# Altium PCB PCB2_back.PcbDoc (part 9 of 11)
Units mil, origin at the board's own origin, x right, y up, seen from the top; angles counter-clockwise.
Board outline 6299 x 3937 mil, 4 copper layers (TopLayer, GROUND, VCC, BottomLayer); 290 components, 470 nets, 2252 pads, 825 vias.
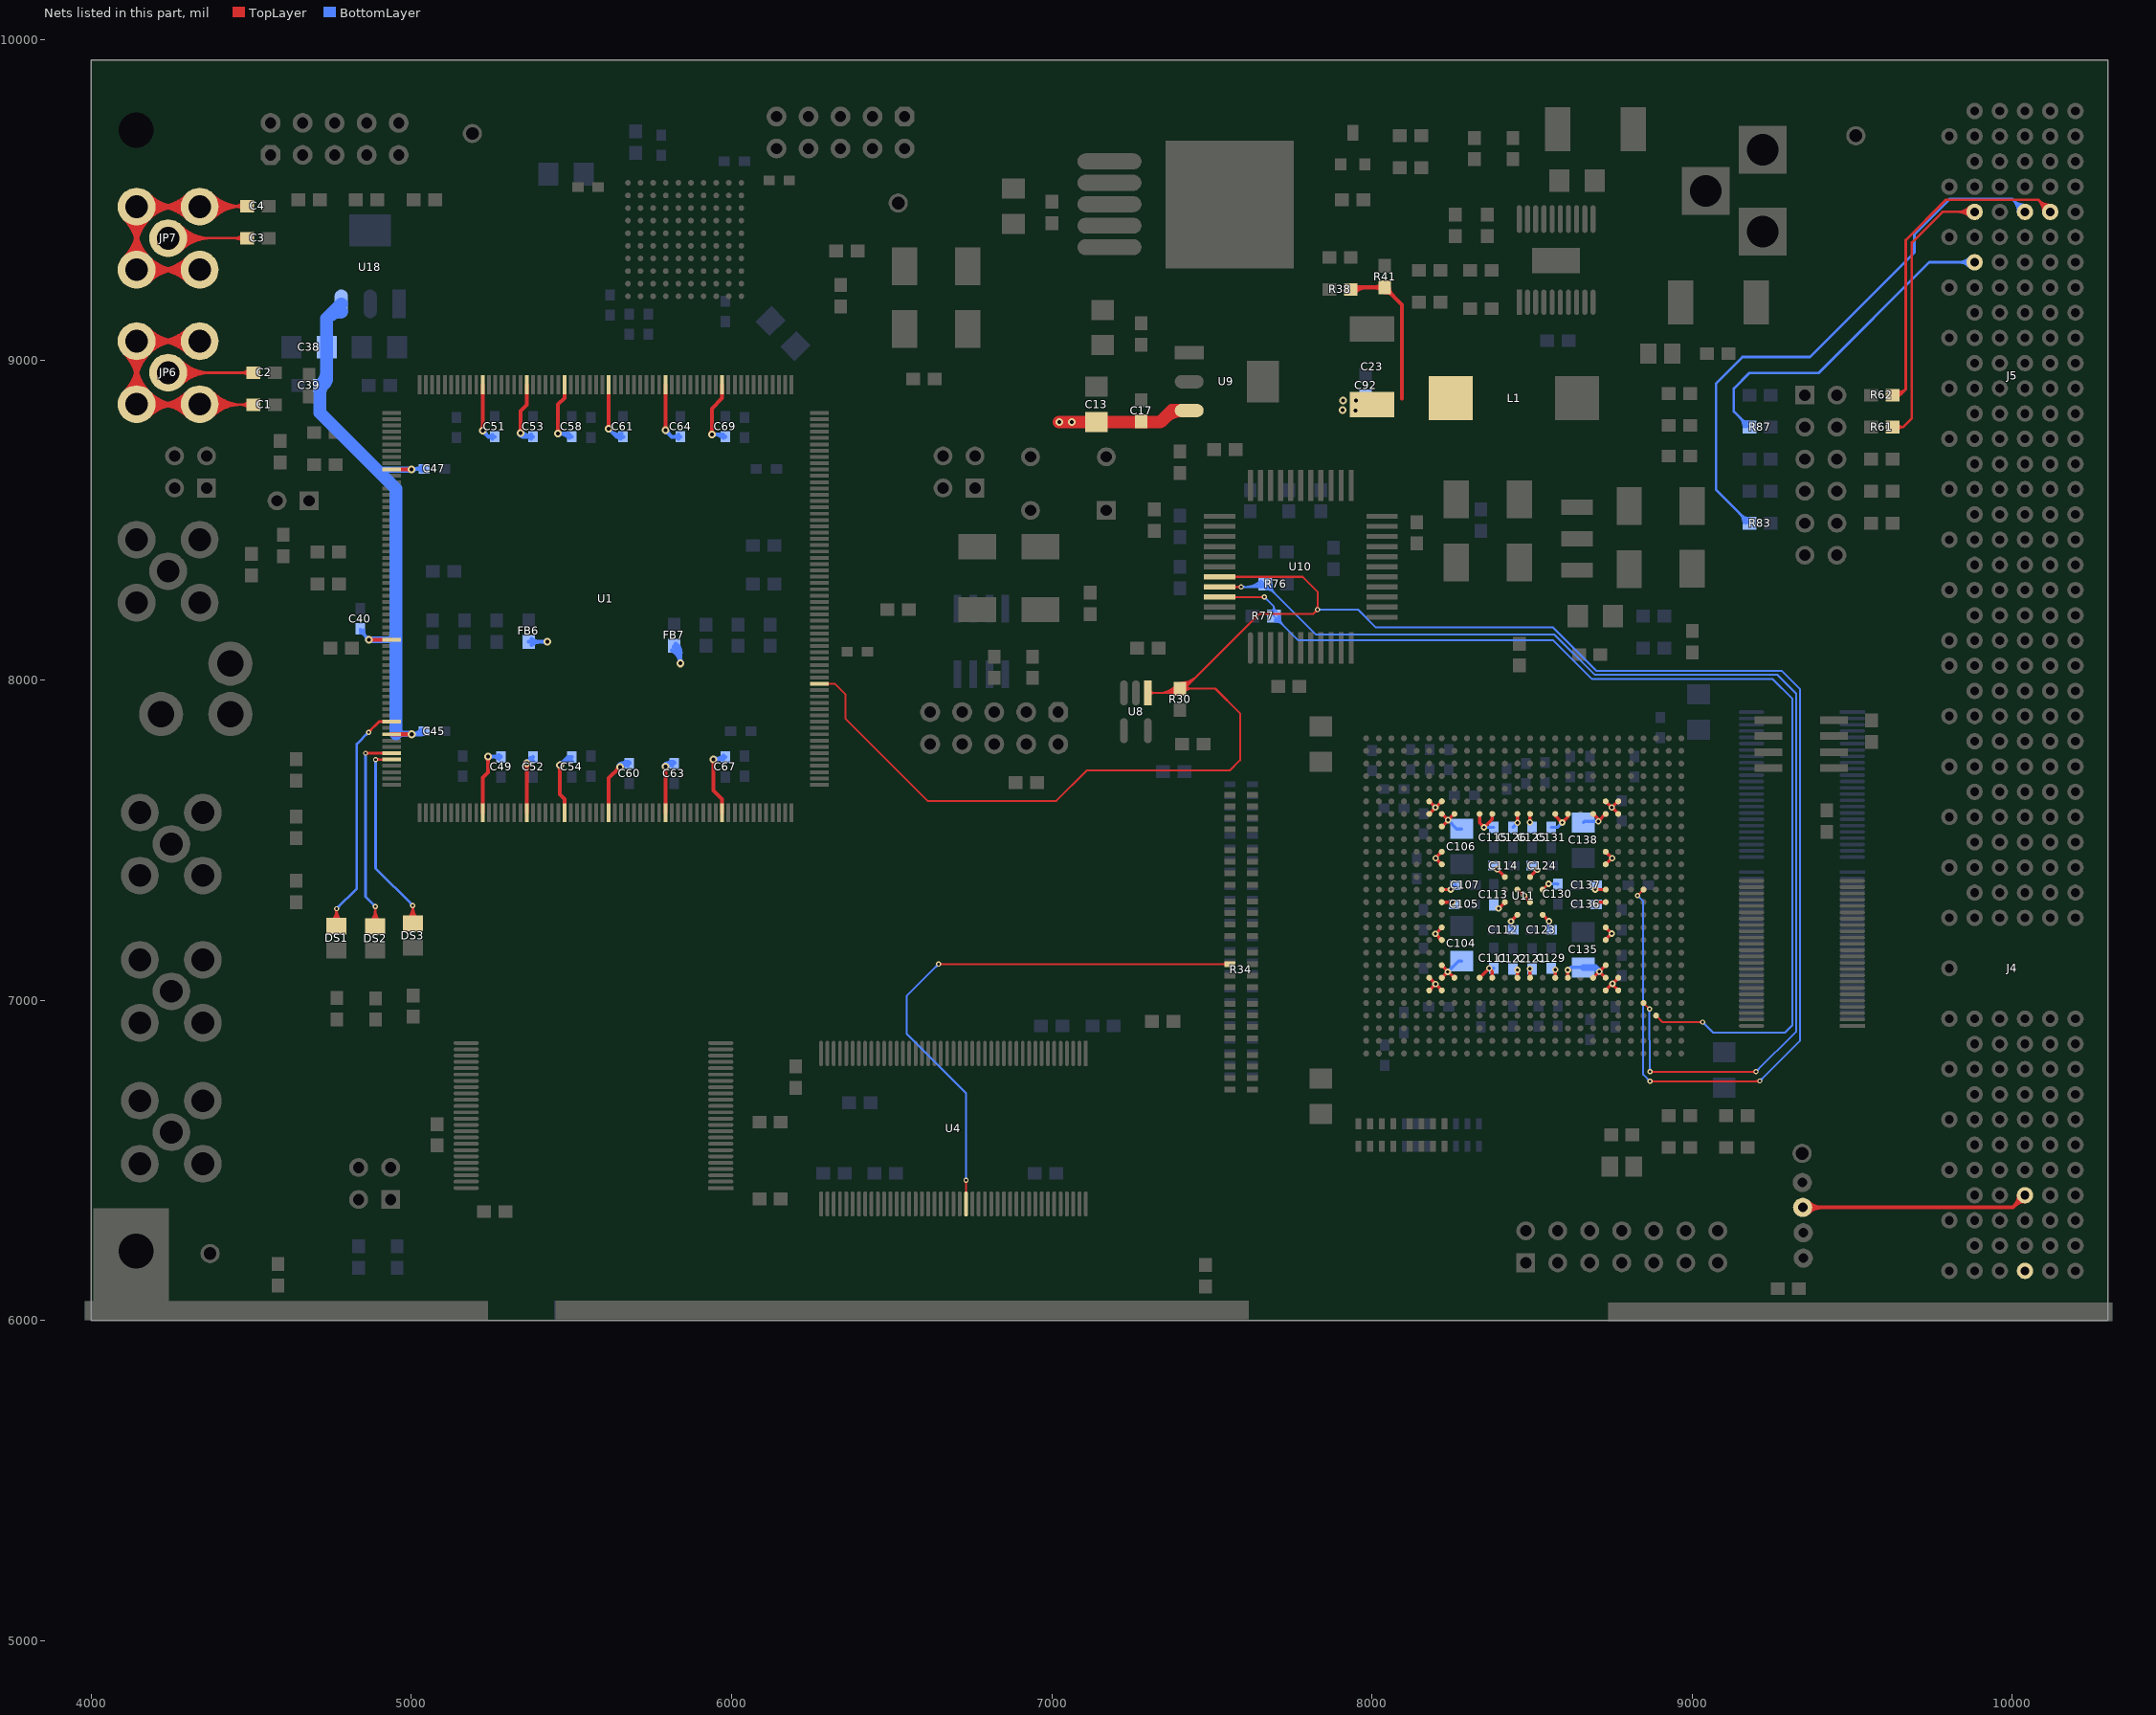
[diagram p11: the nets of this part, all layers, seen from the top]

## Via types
v1: diameter 16, hole 8, TopLayer to BottomLayer, 408 vias
v2: diameter 20, hole 10, TopLayer to BottomLayer, 221 vias
v3: diameter 24, hole 12, TopLayer to BottomLayer, 194 vias
v4: diameter 56.69, hole 56.69, TopLayer to BottomLayer, 2 vias

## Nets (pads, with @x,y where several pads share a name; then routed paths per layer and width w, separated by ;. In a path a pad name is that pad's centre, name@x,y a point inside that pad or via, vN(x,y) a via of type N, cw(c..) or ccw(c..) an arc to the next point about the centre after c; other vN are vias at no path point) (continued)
PXI_TRIG4: J5.B18 R62.1 | length 1277.1
  TopLayer w8: R62.1@9625.46,8890 9649,8890 ; R62.1@9627.28,8889.73 ccw(c9637.47,8907.76) 9652.11,8893.11 ; R62.1@9631.21,8896.69 ccw(c9642.84,8917.27) 9659.56,8900.56 ; R62.1@9635.15,8903.66 ccw(c9648.22,8926.78) 9667,8908 ; R62.1@9642.36,8885.17 cw(c9649,8883.02) 9649,8890 ; R62.1@9642.36,8894.83 ccw(c9649,8896.98) 9649,8890 ; J5.B18@10096.52,9462.27 ccw(c10044.4,9462.27) 10081.25,9499.13 ccw(c10118.11,9535.98) J5.B18@10118.11,9483.86 ; J5.B18@10104.52,9462.27 ccw(c10071.71,9462.27) 10094.91,9485.47 ccw(c10118.11,9508.67) J5.B18@10118.11,9475.86 ; J5.B18@10118.11,9462.27 10080.38,9500 9793,9500 9667,9374 9667,8908 ; 9649,8890 9667,8908
PXI_TRIG5: J5.C18 R83.2 | length 1944.3
  BottomLayer w8: 9148.4,8520.14 cw(c9118.26,8490) R83.2@9160.88,8490 ; 9153.15,8515.38 ccw(c9176.57,8538.8) R83.2@9176.57,8505.68 ; R83.2@9162.06,8506.48 cw(c9145.58,8490) R83.2@9168.88,8490 ; R83.2@9178.54,8490 9074,8594.54 9074,8926 9157,9009 9368,9009 9694,9335 9694,9392 9804,9502 9999.64,9502 J5.C18@10039.37,9462.27 ; J5.C18@10017.78,9462.27 ccw(c9965.66,9462.27) 10002.51,9499.13 ccw(c10039.37,9535.98) J5.C18@10039.37,9483.86 ; J5.C18@10025.78,9462.27 ccw(c9992.97,9462.27) 10016.17,9485.47 ccw(c10039.37,9508.67) J5.C18@10039.37,9475.86
PXI_TRIG6: J5.E18 R61.1 | length 1030.9
  TopLayer w8: R61.1@9625.46,8790 9658,8790 ; R61.1@9640.18,8780.85 cw(c9658,8768.06) 9658,8790 ; R61.1@9640.18,8799.15 ccw(c9658,8811.94) 9658,8790 ; J5.E18@9866.62,9447 ccw(c9829.77,9410.14) 9829.77,9462.27 ccw(c9829.77,9514.39) J5.E18@9866.62,9477.53 ; J5.E18@9872.28,9452.66 ccw(c9849.08,9429.46) 9849.08,9462.27 ccw(c9849.08,9495.08) J5.E18@9872.28,9471.88 ; J5.E18@9881.89,9462.27 9782.27,9462.27 9686,9366 9686,8818 9658,8790
PXI_TRIG7: J5.E16 R87.2 | length 1267.3
  BottomLayer w8: 9148.4,8820.14 cw(c9118.26,8790) R87.2@9160.88,8790 ; 9153.15,8815.38 ccw(c9176.57,8838.8) R87.2@9176.57,8805.68 ; R87.2@9162.06,8806.48 cw(c9145.58,8790) R87.2@9168.88,8790 ; R87.2@9178.54,8790 9130,8838.54 9130,8911 9178,8959 9395,8959 9740.79,9304.79 J5.E16@9881.89,9304.79 ; J5.E16@9866.62,9289.52 ccw(c9829.77,9252.66) 9829.77,9304.79 ccw(c9829.77,9356.91) J5.E16@9866.62,9320.05 ; J5.E16@9872.28,9295.18 ccw(c9849.08,9271.98) 9849.08,9304.79 ccw(c9849.08,9337.6) J5.E16@9872.28,9314.4
PXI_TRST#: J4.C1
PXI_VIO: J4.C4 pad.2@9345,6353 | length 875.6
  TopLayer w12: pad.2@9345,6353 10000.97,6353 J4.C4@10039.37,6391.4 ; pad.2@9361.97,6336.03 cw(c9402.94,6295.06) 9402.94,6353 cw(c9402.94,6410.94) pad.2@9361.97,6369.97 ; J4.C4@10019.78,6391.4 cw(c9972.48,6391.4) 10005.93,6357.96 cw(c10039.37,6324.52) J4.C4@10039.37,6371.81
SCL: R76.2 U10.41 U11.E4 | length 4128.5
  TopLayer w6: U10.41@7523.54,8290.94 v1(7591.06,8290.94) ; U10.41@7568.33,8287.5 cw(c7576.65,8279.18) 7576.65,8290.94 cw(c7576.65,8302.71) U10.41@7568.33,8294.39 ; v1@7587.52,8287.41 ccw(c7578.98,8278.87) 7578.98,8290.94 ccw(c7578.98,8303.02) v1@7587.52,8294.48 ; U11.E4@8847.89,6991.48 v1(8866.37,6973) ; v1(8868,6777) v1(9199,6777) ; v1@8871.54,6773.46 cw(c8880.07,6764.93) 8880.07,6777 cw(c8880.07,6789.07) v1@8871.54,6780.54 ; v1@9195.46,6773.46 ccw(c9186.93,6764.93) 9186.93,6777 ccw(c9186.93,6789.07) v1@9195.46,6780.54
  BottomLayer w6: v1(7591.06,8290.94) R76.2@7665.06,8290.94 ; v1@7594.59,8287.41 cw(c7603.13,8278.87) 7603.13,8290.94 cw(c7603.13,8303.02) v1@7594.59,8294.48 ; 7602.42,8290.94 ccw(c7602.42,8362.14) R76.2@7652.77,8311.8 ; 7616.91,8290.94 ccw(c7616.91,8347.66) R76.2@7657.01,8307.56 ; 7631.4,8290.94 ccw(c7631.4,8333.17) R76.2@7661.25,8303.31 ; R76.2@7645.88,8290.94 ccw(c7645.88,8318.69) R76.2@7665.5,8299.07 ; R76.2@7646.15,8290.94 cw(c7646.15,8281.58) R76.2@7652.77,8288.2 ; R76.2@7666.54,8300 7824.54,8142 8570.03,8142 8695.03,8017 9265,8017 9325,7957 9325,6903 v1(9199,6777) ; R76.2@7668.5,8283.32 cw(c7668.5,8247.79) 7693.63,8272.91 ; R76.2@7668.5,8289.32 cw(c7668.5,8268.27) R76.2@7683.38,8283.15 ; R76.2@7679.19,8300 ccw(c7709.74,8300) 7688.14,8278.4 ; R76.2@7685.19,8300 ccw(c7730.22,8300) 7698.38,8268.16 ; v1@8864.44,6780.51 ccw(c8855.83,6788.97) 8867.9,6789.07 ccw(c8879.97,6789.17) v1@8871.51,6780.56 ; v1@8866.37,6778.63 v1(8868,6777) v1(8866.37,6973) ; v1@9199,6782 ccw(c9199,6794.07) 9207.54,6785.54 ccw(c9216.07,6777) v1@9204,6777
SDA: R77.2 U10.42 U11.D3 | length 3649.1
  TopLayer w6: U10.42@7523.54,8259.45 v1(7663.55,8259.45) ; U10.42@7568.33,8256 cw(c7576.65,8247.68) 7576.65,8259.45 cw(c7576.65,8271.22) U10.42@7568.33,8262.9 ; v1@7660.02,8255.91 ccw(c7651.48,8247.38) 7651.48,8259.45 ccw(c7651.48,8271.52) v1@7660.02,8262.98 ; U11.D3@8887.26,6952.11 8907.37,6932 v1(9033,6932) ; v1@9029.46,6928.46 ccw(c9020.93,6919.93) 9020.93,6932 ccw(c9020.93,6944.07) v1@9029.46,6935.54
  BottomLayer w6: v1@7663.55,8254.45 cw(c7663.55,8242.38) 7672.09,8250.91 cw(c7680.62,8259.45) v1@7668.55,8259.45 ; v1(7663.55,8259.45) 7693.46,8229.54 ; R77.2@7684.85,8214.29 ccw(c7675.67,8229.53) 7693.46,8229.53 ; R77.2@7695.43,8183.31 cw(c7695.43,8147.79) 7720.56,8172.91 ; R77.2@7695.43,8189.31 cw(c7695.43,8168.27) R77.2@7710.31,8183.15 ; R77.2@7702.08,8214.29 cw(c7711.26,8229.53) 7693.46,8229.53 ; R77.2@7706.12,8200 ccw(c7736.67,8200) 7715.07,8178.4 ; R77.2@7712.12,8200 ccw(c7757.15,8200) 7725.31,8168.16 ; v1@9033,6927 cw(c9033,6914.93) 9041.54,6923.46 cw(c9050.07,6932) v1@9038,6932 ; v1(9033,6932) 9066,6899 9289,6899 9313,6923 9313,7941 9250,8004 8686,8004 8565,8125 7768.46,8125 R77.2@7693.46,8200 7693.46,8229.54
SDCKE: R34.6 U4.67 | length 1886.9
  TopLayer w6: v1(6646,7113) R34.6@7555.84,7113 ; v1@6649.54,7109.46 cw(c6658.07,7100.93) 6658.07,7113 cw(c6658.07,7125.07) v1@6649.54,7116.54 ; v1@6728.45,6434.45 cw(c6719.91,6425.91) 6731.98,6425.91 cw(c6744.06,6425.91) v1@6735.52,6434.45 ; U4.67@6729.93,6399.52 ccw(c6724.97,6404.48) 6731.99,6404.48 ccw(c6739,6404.48) U4.67@6734.04,6399.52 ; U4.67@6731.98,6364 v1(6731.98,6437.98) ; R34.6@7543.1,7108.76 ccw(c7532.86,7098.51) 7532.86,7113 ccw(c7532.86,7127.49) R34.6@7543.1,7117.24
  BottomLayer w6: v1@6641,7113 cw(c6628.93,7113) 6637.46,7104.46 cw(c6646,7095.93) v1@6646,7108 ; v1(6646,7113) 6546,7013 6546,6896 6731.98,6710.02 v1(6731.98,6437.98) ; v1@6728.45,6441.52 ccw(c6719.91,6450.06) 6731.98,6450.06 ccw(c6744.06,6450.06) v1@6735.52,6441.52
SERIN+: C2.2 JP6.1 | length 979.1
  TopLayer w8: JP6.1@4240,8960 C2.2@4506.54,8960 ; JP6.1@4261.96,8938.04 cw(c4314.97,8885.03) 4314.97,8960 cw(c4314.97,9034.97) JP6.1@4261.96,8981.96 ; JP6.1@4267.62,8932.38 cw(c4334.29,8865.71) 4334.29,8960 cw(c4334.29,9054.29) JP6.1@4267.62,8987.62 ; JP6.1@4273.27,8926.73 cw(c4353.6,8846.4) 4353.6,8960 cw(c4353.6,9073.6) JP6.1@4273.27,8993.27 ; JP6.1@4278.93,8921.07 cw(c4372.91,8827.09) 4372.91,8960 cw(c4372.91,9092.91) JP6.1@4278.93,8998.93 ; C2.2@4493.48,8948.91 ccw(c4466.7,8922.13) 4466.7,8960 ccw(c4466.7,8997.87) C2.2@4493.48,8971.09
SERIN-: C1.2 JP6.2 | length 5536.6
  TopLayer w6: JP6.2@4338.43,8861.58 JP6.2@4340,8860
  TopLayer w8: JP6.2@4102.65,8900.5 ccw(c4008.66,8994.49) 4141.57,8994.49 ccw(c4274.49,8994.49) 4180.5,8900.5 ccw(c4279.32,8999.32) 4279.32,8859.57 ; JP6.2@4102.65,9019.5 cw(c4008.66,8925.51) 4141.57,8925.51 cw(c4274.49,8925.51) 4180.5,9019.5 cw(c4274.49,8925.51) 4274.49,9058.43 ; JP6.2@4108.3,8894.85 ccw(c4027.97,8975.18) 4141.57,8975.18 ccw(c4255.18,8975.18) 4174.85,8894.85 ccw(c4260,8980) 4260,8859.57 ; JP6.2@4108.3,9025.15 cw(c4027.97,8944.82) 4141.57,8944.82 cw(c4255.18,8944.82) 4174.85,9025.15 cw(c4255.18,8944.82) 4255.18,9058.42 cw(c4255.18,9172.03) JP6.2@4174.85,9091.7 ; JP6.2@4113.96,8889.19 ccw(c4047.29,8955.86) 4141.57,8955.86 ccw(c4235.86,8955.86) 4169.19,8889.19 ccw(c4240.69,8960.69) 4240.69,8859.58 ; JP6.2@4113.96,9030.81 cw(c4047.29,8964.14) 4141.57,8964.14 cw(c4235.86,8964.14) 4169.19,9030.81 cw(c4235.86,8964.14) 4235.86,9058.42 ; JP6.2@4119.62,8883.53 ccw(c4066.6,8936.55) 4141.57,8936.55 ccw(c4216.55,8936.55) 4163.53,8883.53 ccw(c4221.38,8941.38) 4221.38,8859.58 ; JP6.2@4119.62,9036.47 cw(c4066.6,8983.45) 4141.57,8983.45 cw(c4216.55,8983.45) 4163.53,9036.47 cw(c4216.55,8983.45) 4216.55,9058.43 ; JP6.2@4157.88,8877.88 ccw(c4202.06,8922.06) 4202.06,8859.57 ; JP6.2@4163.53,8839.62 cw(c4211.72,8791.43) 4211.72,8859.58 ; JP6.2@4163.53,9080.38 ccw(c4216.55,9133.4) 4216.55,9058.42 ; JP6.2@4169.19,8833.96 cw(c4231.03,8772.12) 4231.03,8859.57 ; JP6.2@4169.19,9086.04 ccw(c4235.86,9152.71) 4235.86,9058.43 ; JP6.2@4174.85,8828.3 cw(c4250.35,8752.8) 4250.35,8859.58 ; JP6.2@4180.5,8822.65 cw(c4269.66,8733.49) 4269.66,8859.58 ; JP6.2@4180.5,9097.35 ccw(c4274.49,9191.34) 4274.49,9058.42 ; 4200.68,8859.57 ccw(c4200.68,8999.32) JP6.2@4299.5,8900.5 ; 4205.51,9058.42 ccw(c4205.51,9191.34) JP6.2@4299.5,9097.35 ; 4205.51,9058.43 cw(c4205.51,8925.51) JP6.2@4299.5,9019.5 ; 4210.34,8859.58 cw(c4210.34,8733.49) JP6.2@4299.5,8822.65 ; 4220,8859.57 ccw(c4220,8980) JP6.2@4305.15,8894.85 ; 4229.65,8859.58 cw(c4229.65,8752.8) JP6.2@4305.15,8828.3 ; 4239.31,8859.58 ccw(c4239.31,8960.69) JP6.2@4310.81,8889.19 ; 4244.14,9058.42 cw(c4244.14,8964.14) JP6.2@4310.81,9030.81 ; 4244.14,9058.43 ccw(c4244.14,9152.71) JP6.2@4310.81,9086.04 ; 4248.97,8859.57 cw(c4248.97,8772.12) JP6.2@4310.81,8833.96 ; 4258.62,8859.58 ccw(c4258.62,8941.38) JP6.2@4316.47,8883.53 ; 4263.45,9058.42 ccw(c4263.45,9133.4) JP6.2@4316.47,9080.38 ; 4263.45,9058.43 cw(c4263.45,8983.45) JP6.2@4316.47,9036.47 ; 4268.28,8859.58 cw(c4268.28,8791.43) JP6.2@4316.47,8839.62 ; 4277.94,8859.57 ccw(c4277.94,8922.06) JP6.2@4322.12,8877.88 ; JP6.2@4305.15,9025.15 ccw(c4224.82,8944.82) 4224.82,9058.42 ccw(c4224.82,9172.03) JP6.2@4305.15,9091.7 ; JP6.2@4336.43,8859.58 4141.57,8859.58 JP6.2@4141.57,9058.42 JP6.2@4338.43,9058.42 ; JP6.2@4340,8860 C1.2@4506.54,8860 ; JP6.2@4354.73,8877.88 ccw(c4397.89,8921.04) 4397.89,8860 ; JP6.2@4360.38,8839.62 cw(c4409.6,8790.4) 4409.6,8860 ; JP6.2@4360.38,8883.53 ccw(c4417.2,8940.35) 4417.2,8860 ; JP6.2@4366.04,8833.96 cw(c4428.91,8771.09) 4428.91,8860 ; JP6.2@4366.04,8889.19 ccw(c4436.51,8959.66) 4436.51,8860 ; JP6.2@4371.7,8828.3 cw(c4448.22,8751.78) 4448.22,8860 ; JP6.2@4371.7,8894.85 ccw(c4455.83,8978.98) 4455.83,8860 ; JP6.2@4377.35,8822.65 cw(c4467.54,8732.46) 4467.54,8860 ; JP6.2@4377.35,8900.5 ccw(c4475.14,8998.29) 4475.14,8860 ; C1.2@4493.48,8848.91 ccw(c4466.7,8822.13) 4466.7,8860 ccw(c4466.7,8897.87) C1.2@4493.48,8871.09
SEROUT+: C3.2 JP7.1 | length 959.1
  TopLayer w8: JP7.1@4240,9380 C3.2@4486.54,9380 ; JP7.1@4261.96,9358.04 cw(c4314.97,9305.03) 4314.97,9380 cw(c4314.97,9454.97) JP7.1@4261.96,9401.96 ; JP7.1@4267.62,9352.38 cw(c4334.29,9285.71) 4334.29,9380 cw(c4334.29,9474.29) JP7.1@4267.62,9407.62 ; JP7.1@4273.27,9346.73 cw(c4353.6,9266.4) 4353.6,9380 cw(c4353.6,9493.6) JP7.1@4273.27,9413.27 ; JP7.1@4278.93,9341.07 cw(c4372.91,9247.09) 4372.91,9380 cw(c4372.91,9512.91) JP7.1@4278.93,9418.93 ; C3.2@4473.48,9368.91 ccw(c4446.7,9342.13) 4446.7,9380 ccw(c4446.7,9417.87) C3.2@4473.48,9391.09
SEROUT-: C4.2 JP7.2 | length 5418.4
  TopLayer w8: JP7.2@4102.65,9320.5 ccw(c4008.66,9414.49) 4141.57,9414.49 ccw(c4274.49,9414.49) 4180.5,9320.5 ccw(c4274.49,9414.49) 4274.49,9281.57 ; JP7.2@4102.65,9439.5 cw(c4008.66,9345.51) 4141.57,9345.51 cw(c4274.49,9345.51) 4180.5,9439.5 cw(c4274.49,9345.51) 4274.49,9478.43 ; JP7.2@4108.3,9314.85 ccw(c4027.97,9395.18) 4141.57,9395.18 ccw(c4255.18,9395.18) 4174.85,9314.85 ccw(c4255.18,9395.18) 4255.18,9281.58 ccw(c4255.18,9167.97) JP7.2@4174.85,9248.3 ; JP7.2@4108.3,9445.15 cw(c4027.97,9364.82) 4141.57,9364.82 cw(c4255.18,9364.82) 4174.85,9445.15 cw(c4255.18,9364.82) 4255.18,9478.42 cw(c4255.18,9592.03) JP7.2@4174.85,9511.7 ; JP7.2@4113.96,9309.19 ccw(c4047.29,9375.86) 4141.57,9375.86 ccw(c4235.86,9375.86) 4169.19,9309.19 ccw(c4235.86,9375.86) 4235.86,9281.58 ; JP7.2@4113.96,9450.81 cw(c4047.29,9384.14) 4141.57,9384.14 cw(c4235.86,9384.14) 4169.19,9450.81 cw(c4235.86,9384.14) 4235.86,9478.42 ; JP7.2@4119.62,9303.53 ccw(c4066.6,9356.55) 4141.57,9356.55 ccw(c4216.55,9356.55) 4163.53,9303.53 ccw(c4216.55,9356.55) 4216.55,9281.57 ; JP7.2@4119.62,9456.47 cw(c4066.6,9403.45) 4141.57,9403.45 cw(c4216.55,9403.45) 4163.53,9456.47 cw(c4216.55,9403.45) 4216.55,9478.43 ; JP7.2@4163.53,9259.62 cw(c4216.55,9206.6) 4216.55,9281.58 ; JP7.2@4163.53,9500.38 ccw(c4216.55,9553.4) 4216.55,9478.42 ; JP7.2@4169.19,9253.96 cw(c4235.86,9187.29) 4235.86,9281.57 ; JP7.2@4169.19,9506.04 ccw(c4235.86,9572.71) 4235.86,9478.43 ; JP7.2@4180.5,9242.65 cw(c4274.49,9148.66) 4274.49,9281.58 ; JP7.2@4180.5,9517.35 ccw(c4274.49,9611.34) 4274.49,9478.42 ; 4205.51,9281.57 ccw(c4205.51,9414.49) JP7.2@4299.5,9320.5 ; 4205.51,9281.58 cw(c4205.51,9148.66) JP7.2@4299.5,9242.65 ; 4205.51,9478.42 ccw(c4205.51,9611.34) JP7.2@4299.5,9517.35 ; 4205.51,9478.43 cw(c4205.51,9345.51) JP7.2@4299.5,9439.5 ; 4244.14,9281.57 cw(c4244.14,9187.29) JP7.2@4310.81,9253.96 ; 4244.14,9281.58 ccw(c4244.14,9375.86) JP7.2@4310.81,9309.19 ; 4244.14,9478.42 cw(c4244.14,9384.14) JP7.2@4310.81,9450.81 ; 4244.14,9478.43 ccw(c4244.14,9572.71) JP7.2@4310.81,9506.04 ; 4263.45,9281.57 ccw(c4263.45,9356.55) JP7.2@4316.47,9303.53 ; 4263.45,9281.58 cw(c4263.45,9206.6) JP7.2@4316.47,9259.62 ; 4263.45,9478.42 ccw(c4263.45,9553.4) JP7.2@4316.47,9500.38 ; 4263.45,9478.43 cw(c4263.45,9403.45) JP7.2@4316.47,9456.47 ; JP7.2@4305.15,9248.3 ccw(c4224.82,9167.97) 4224.82,9281.58 ccw(c4224.82,9395.18) JP7.2@4305.15,9314.85 ; JP7.2@4305.15,9445.15 ccw(c4224.82,9364.82) 4224.82,9478.42 ccw(c4224.82,9592.03) JP7.2@4305.15,9511.7 ; JP7.2@4338.43,9281.58 JP7.2@4141.57,9281.58 JP7.2@4141.57,9478.42 JP7.2@4338.43,9478.42 4340,9480 C4.2@4486.54,9480 ; JP7.2@4354.73,9462.12 cw(c4397.89,9418.96) 4397.89,9480 ; JP7.2@4360.38,9456.47 cw(c4417.2,9399.65) 4417.2,9480 ; JP7.2@4360.38,9500.38 ccw(c4409.6,9549.6) 4409.6,9480 ; JP7.2@4366.04,9450.81 cw(c4436.51,9380.34) 4436.51,9480 ; JP7.2@4366.04,9506.04 ccw(c4428.91,9568.91) 4428.91,9480 ; JP7.2@4371.7,9445.15 cw(c4455.83,9361.02) 4455.83,9480 ; JP7.2@4371.7,9511.7 ccw(c4448.22,9588.22) 4448.22,9480 ; JP7.2@4377.35,9439.5 cw(c4475.14,9341.71) C4.2@4475.14,9480 ; JP7.2@4377.35,9517.35 ccw(c4467.54,9607.54) C4.2@4467.54,9480 ; C4.2@4473.48,9468.91 ccw(c4446.7,9442.13) 4446.7,9480 ccw(c4446.7,9517.87) C4.2@4473.48,9491.09
SYSTEM_RESET#: R30.1 U1.17 U8.1 U10.40 U11.P4 | length 7449.2
  TopLayer w6: U1.17@6274.31,7988.25 6322.75,7988.25 6356,7955 6356,7879 6612,7623 7014,7623 7109,7718 7556,7718 7588,7750 7588,7896 7510.54,7973.46 R30.1@7400,7973.46 7386.54,7960 U8.1@7300,7960 ; U1.17@6299.98,7986.2 cw(c6304.94,7981.24) 6304.94,7988.25 cw(c6304.94,7995.27) U1.17@6299.98,7990.31 ; U8.1@7306.23,7953.77 cw(c7321.27,7938.73) 7321.27,7960 cw(c7321.27,7981.27) U8.1@7306.23,7966.23 ; 7331.96,7960 ccw(c7331.96,8039.53) R30.1@7388.2,7983.29 ; 7346.45,7960 ccw(c7346.45,8025.05) R30.1@7392.44,7979.05 ; 7360.94,7960 ccw(c7360.94,8010.56) R30.1@7396.69,7974.81 ; 7375.42,7960 ccw(c7375.42,7996.08) R30.1@7400.93,7970.57 ; R30.1@7400,7974.12 ccw(c7400,8010.62) 7425.81,7984.81 ; R30.1@7400,7980.12 ccw(c7400,8031.1) 7436.05,7995.05 ; R30.1@7400,7986.12 ccw(c7400,8051.59) 7446.29,8005.29 ; R30.1@7400,7992.12 ccw(c7400,8072.07) 7456.54,8015.54 ; R30.1@7407.56,7965.91 cw(c7425.8,7947.67) 7425.8,7973.46 cw(c7425.8,7999.26) R30.1@7407.56,7981.02 ; R30.1@7411.8,7961.67 cw(c7440.28,7933.18) 7440.28,7973.46 cw(c7440.28,8013.75) R30.1@7411.8,7985.26 ; R30.1@7414.46,7973.46 7648,8207 7817,8207 v1(7830,8220) 7830,8276 7783.56,8322.44 U10.40@7523.54,8322.44 ; U10.40@7568.33,8318.99 cw(c7576.65,8310.67) 7576.65,8322.44 cw(c7576.65,8334.21) U10.40@7568.33,8325.89 ; v1@7825,8220 cw(c7812.93,8220) 7821.46,8211.46 cw(c7830,8202.93) v1@7830,8215 ; v1@7826.46,8223.54 ccw(c7817.93,8232.07) 7830,8232.07 ccw(c7842.07,8232.07) v1@7833.54,8223.54 ; v1(8829,7326.92) U11.P4@8847.89,7345.81 ; v1(8868,6747) 9211,6747 v1(9211,6748) ; v1@8871.54,6743.46 cw(c8880.07,6734.93) 8880.07,6747 cw(c8880.07,6759.07) v1@8871.54,6750.54 ; 9196.51,6747 ccw(c9196.51,6762.49) v1@9207.46,6751.54 ; 9201.34,6747 cw(c9201.34,6738.34) v1@9207.46,6744.46
  BottomLayer w6: v1(7830,8220) 7956,8220 8011,8165 8564,8165 8700,8029 9279,8029 9337,7971 9337,6874 v1(9211,6748) ; v1@7833.54,8216.46 cw(c7842.07,8207.93) 7842.07,8220 cw(c7842.07,8232.07) v1@7833.54,8223.54 ; v1(8829,7326.92) 8847,7308.92 8847,6768 v1(8868,6747) ; v1@8863,6747 ccw(c8850.93,6747) 8859.46,6755.54 ccw(c8868,6764.07) v1@8868,6752 ; v1@9211,6753 ccw(c9211,6765.07) 9219.54,6756.54 ccw(c9228.07,6748) v1@9216,6748
USER_LED0: DS3.1 U1.176 | length 804.4
  TopLayer w8: v1(4888.03,7752.03) U1.176@4937.69,7752.03 ; v1@4890.86,7749.2 cw(c4897.69,7742.37) 4897.69,7752.03 cw(c4897.69,7761.69) v1@4890.86,7754.86 ; DS3.1@4988.73,7254.67 ccw(c4951.88,7291.53) 5004,7291.53 ccw(c5056.12,7291.53) DS3.1@5019.27,7254.67 ; DS3.1@4994.39,7249.01 ccw(c4971.19,7272.21) 5004,7272.21 ccw(c5036.81,7272.21) DS3.1@5013.61,7249.01 ; v1@5001.17,7293.17 cw(c4994.34,7286.34) 5004,7286.34 cw(c5013.66,7286.34) v1@5006.83,7293.17 ; DS3.1@5004,7239.4 v1(5004,7296)
  BottomLayer w8: v1@4885.2,7749.2 cw(c4878.37,7742.37) 4888.03,7742.37 cw(c4897.69,7742.37) v1@4890.86,7749.2 ; v1(4888.03,7752.03) 4888.03,7411.97 v1(5004,7296) ; v1@5000,7296 ccw(c4990.34,7296) 4997.17,7302.83 ccw(c5004,7309.66) v1@5004,7300
USER_LED1: DS2.1 U1.175 | length 828.9
  TopLayer w8: v1(4856.72,7771.72) U1.175@4937.69,7771.72 ; v1@4859.54,7768.89 cw(c4866.37,7762.06) 4866.37,7771.72 cw(c4866.37,7781.37) v1@4859.54,7774.54 ; DS2.1@4871.73,7245.67 ccw(c4834.88,7282.53) 4887,7282.53 ccw(c4939.12,7282.53) DS2.1@4902.27,7245.67 ; DS2.1@4877.39,7240.01 ccw(c4854.19,7263.21) 4887,7263.21 ccw(c4919.81,7263.21) DS2.1@4896.61,7240.01 ; v1@4884.17,7290.17 cw(c4877.34,7283.34) 4887,7283.34 cw(c4896.66,7283.34) v1@4889.83,7290.17 ; DS2.1@4887,7230.4 v1(4887,7293)
  BottomLayer w8: v1@4853.89,7768.89 cw(c4847.06,7762.06) 4856.72,7762.06 cw(c4866.37,7762.06) v1@4859.54,7768.89 ; v1(4856.72,7771.72) 4856.72,7323.28 v1(4887,7293) ; v1@4883,7293 ccw(c4873.34,7293) 4880.17,7299.83 ccw(c4887,7306.66) v1@4887,7297
USER_LED2: DS1.1 U1.170 | length 926.5
  TopLayer w8: DS1.1@4750.73,7246.67 ccw(c4713.88,7283.53) 4766,7283.53 ccw(c4818.12,7283.53) DS1.1@4781.27,7246.67 ; DS1.1@4756.39,7241.01 ccw(c4733.19,7264.21) 4766,7264.21 ccw(c4798.81,7264.21) DS1.1@4775.61,7241.01 ; v1@4763.17,7283.17 cw(c4756.34,7276.34) 4766,7276.34 cw(c4775.66,7276.34) v1@4768.83,7283.17 ; DS1.1@4766,7231.4 v1(4766,7286) ; v1(4866,7837) 4899.14,7870.14 U1.170@4937.69,7870.14 ; v1@4866,7841 ccw(c4866,7850.66) 4872.83,7843.83 ccw(c4879.66,7837) v1@4870,7837
  BottomLayer w8: v1(4766,7286) 4829,7349 4829,7800 v1(4866,7837) ; v1@4766,7290 ccw(c4766,7299.66) 4772.83,7292.83 ccw(c4779.66,7286) v1@4770,7286 ; v1@4862,7837 cw(c4852.34,7837) 4859.17,7830.17 cw(c4866,7823.34) v1@4866,7833
V1.4: C23.1 C92.2 C104.1 C105.2 C106.1 C107.1 C111.1 C112.2 C113.1 C114.1 C115.1 C121.1 C122.1 C123.1 C124.1 C125.1 C126.1 C129.1 C130.2 C131.1 C135.1 C136.1 C137.1 C138.1 L1.2 R38.2 R41.2 U11.AA6 U11.AA7 U11.AA20 U11.AA21 U11.F6 U11.F7 U11.F20 U11.F21 U11.G6 U11.G7 U11.G8 U11.G10 U11.G11 U11.G13 U11.G14 U11.G16 U11.G17 U11.G19 U11.G20 U11.G21 U11.H7 U11.H20 U11.K7 U11.K20 U11.L7 U11.L20 U11.M12 U11.M14 U11.N7 U11.N13 U11.N15 U11.N20 U11.P7 U11.P12 U11.P14 U11.P20 U11.R13 U11.R15 U11.T7 U11.T20 U11.U7 U11.U20 U11.W20 U11.Y6 U11.Y7 U11.Y8 U11.Y10 U11.Y11 U11.Y13 U11.Y14 U11.Y16 U11.Y17 U11.Y19 U11.Y20 U11.Y21 | length 2900
  TopLayer w8: v2@8473,7327 v2@8474,7326 ; U11.P12@8532.93,7345.81 v2(8551.12,7364)
  TopLayer w10: U11.F21@8178.6,7030.85 v2(8198.23,7050.48) ; U11.G21@8178.6,7070.22 U11.F20@8217.97,7030.85 ; U11.Y21@8178.6,7582.03 v2@8198.39,7601.83 ; U11.AA21@8178.6,7621.4 v2(8198.17,7601.83) v2@8198.39,7601.83 ; U11.G20@8217.97,7070.22 v2(8236.57,7088.82) ; U11.H20@8217.97,7109.59 U11.G19@8257.34,7070.22 ; U11.K20@8217.97,7188.33 8217.4,7188.33 v2(8198,7207.73) U11.L20@8217.97,7227.7 ; U11.N20@8217.97,7306.44 v2(8250.57,7306.44) ; U11.P20@8217.97,7345.81 v2(8245.81,7345.81) ; U11.T20@8217.97,7424.55 v2(8199,7443.52) 8199,7444.95 U11.U20@8217.97,7463.92 ; U11.W20@8217.97,7542.66 8237.65,7562.35 v2@8238.12,7562.81 ; U11.Y20@8217.97,7582.03 v2(8237.19,7562.81) v2@8238.12,7562.81 ; U11.AA20@8217.97,7621.4 v2@8198.39,7601.83 ; U11.Y19@8257.34,7582.03 v2@8238.12,7562.81 ; U11.G17@8336.08,7070.22 v2(8365.86,7100) 8375.45,7090.41 U11.G16@8375.45,7070.22 ; U11.Y17@8336.08,7582.03 8336.08,7553.92 v2(8350,7540) 8375.45,7565.45 U11.Y16@8375.45,7582.03 ; v2(8391,7409) U11.R15@8414.82,7385.18 ; v2(8395.38,7287) U11.N15@8414.82,7306.44 ; v2(8434,7246.88) U11.M14@8454.19,7267.07 ; v2(8454,7095) 8454.19,7094.81 U11.G14@8454.19,7070.22 ; U11.P14@8454.19,7345.81 8473,7327 v2(8475,7327) 8493.56,7308.44 U11.N13@8493.56,7306.44 ; v2(8454.19,7554.19) U11.Y14@8454.19,7582.03 ; U11.G13@8493.56,7070.22 v2(8493.56,7098.56) ; U11.R13@8493.56,7385.18 v2(8516,7407.62) ; v2(8493.56,7555.56) U11.Y13@8493.56,7582.03 ; U11.M12@8532.93,7267.07 v2(8553,7247) ; U11.G11@8572.3,7070.22 v2(8572.3,7095.7) ; U11.Y11@8572.3,7582.03 8572.3,7576.7 v2(8594,7555) 8611.67,7572.67 U11.Y10@8611.67,7582.03 ; U11.G10@8611.67,7070.22 v2(8611.67,7094.67) ; U11.G8@8690.41,7070.22 8690.41,7070.41 8729.59,7109.59 U11.H7@8729.78,7109.59 ; U11.Y8@8690.41,7582.03 8706.75,7565.69 v2(8706.75,7559) U11.Y7@8729.78,7582.03 ; v2(8697.19,7345.81) U11.P7@8729.78,7345.81 ; v2(8699.56,7306.44) U11.N7@8729.78,7306.44 ; v2(8710,7090) U11.G7@8729.78,7070.22 ; U11.F7@8729.78,7030.85 U11.G6@8769.15,7070.22 ; U11.K7@8729.78,7188.33 8729.78,7189.26 v2(8749,7208.48) U11.L7@8729.78,7227.7 ; U11.T7@8729.78,7424.55 8748.93,7443.7 v2(8750,7443.7) U11.U7@8729.78,7463.92 ; U11.AA7@8729.78,7621.4 U11.Y6@8769.15,7582.03 ; v2(8748.94,7602.24) 8768.09,7621.4 U11.AA6@8769.15,7621.4 ; v2(8750.67,7051.74) 8750.67,7049.33 U11.F6@8769.15,7030.85 U11.F6@8769.15,7032.32
  TopLayer w12: R38.2@7933.46,9220 7940,9226.54 R41.2@8040,9226.54 8094,9172.54 8094,8879 ; R38.2@7936.62,9218.81 cw(c7955.28,9200.15) 7955.28,9226.54 ; R38.2@7945.11,9210.32 cw(c7984.25,9171.18) 7984.25,9226.54 ; R41.2@8030.32,9216.86 ccw(c8006.96,9193.5) 8006.96,9226.54 ccw(c8006.96,9259.57) R41.2@8030.32,9236.21 ; R41.2@8040,9210.88 cw(c8040,9173.09) 8066.72,9199.81 ; R41.2@8053.68,9224.57 ccw(c8081.97,9224.57) 8061.97,9204.57
  BottomLayer w10: v2(8236.57,7088.82) 8270.31,7122.57 C104.1@8280,7122.57 ; v2(8237.19,7562.81) 8264.88,7535.12 C106.1@8280,7535.12 ; v2(8245.81,7345.81) C107.1@8260,7360 ; v2(8350,7540) C115.1@8380,7540 ; v2(8365.86,7100) C111.1@8380,7100 ; v2(8434,7246.88) 8434,7226.99 C112.2@8440.99,7220 ; C126.1@8440,7540 v2(8454.19,7554.19) ; v2(8551.12,7364) 8578.99,7364 C130.2@8580,7362.99 ; v2(8553,7247) 8553,7227 C123.1@8560,7220 ; C131.1@8560,7540 8579,7540 v2(8594,7555) ; v2(8611.67,7094.67) 8619.57,7102.57 C135.1@8660,7102.57 ; C138.1@8660,7555.12 8663.88,7559 v2(8706.75,7559)
  BottomLayer w12: v3(7949,8842) 7980,8873 C92.2@7980,8886.54 ; v3@7949,8848 ccw(c7949,8862.49) 7959.24,8852.24 ccw(c7969.49,8842) v3@7955,8842 ; v3@7954.78,8847.78 ccw(c7925.65,8876.92) C92.2@7966.45,8882.66 ; 7971.8,8864.8 ccw(c7955.48,8881.11) C92.2@7978.33,8884.33
  BottomLayer w20: C135.1@8660,7102.57 8697.43,7102.57 v2(8710,7090)
  other v3: 7908,8843 7909,8873 7950,8873
V1.5: C13.1 C17.2 C49.1 C51.1 C52.1 C53.1 C54.1 C58.1 C60.1 C61.1 C63.1 C64.1 C67.1 C69.1 FB6.1 FB7.1 U1.72 U1.81 U1.90 U1.97 U1.103 U1.110 U1.191 U1.198 U1.204 U1.211 U1.220 U1.229 U9.3 | length 4596.7
  TopLayer w8: 5220,8857 5222.14,8859.14 ; U1.97@5478.05,8922.31 U1.97@5480,8920.35
  TopLayer w12: v3@5217.9,8783.1 ccw(c5207.66,8793.34) 5222.14,8793.34 ccw(c5236.63,8793.34) v3@5226.38,8783.1 ; U1.191@5222.14,7585.69 5222.14,7695.14 5239,7712 v3(5239,7761) ; v3(5222.14,8778.86) U1.110@5222.14,8922.31 ; v3@5234.76,7756.76 cw(c5224.51,7746.51) 5239,7746.51 cw(c5253.49,7746.51) v3@5243.24,7756.76 ; v3@5336.76,8775.24 ccw(c5326.51,8785.49) 5341,8785.49 ccw(c5355.49,8785.49) v3@5345.24,8775.24 ; v3(5341,8771) 5341,8840.13 5359.94,8859.06 U1.103@5359.94,8922.31 ; v3@5355.69,7735.69 cw(c5345.45,7725.45) 5359.94,7725.45 cw(c5374.42,7725.45) v3@5364.18,7735.69 ; U1.198@5359.94,7585.69 v3(5359.94,7739.94) ; v3@5453.76,8774.24 ccw(c5443.51,8784.49) 5458,8784.49 ccw(c5472.49,8784.49) v3@5462.24,8774.24 ; v3(5458,8770) 5458,8861 5478.05,8881.05 U1.97@5478.05,8922.31 ; v3@5459.76,7730.76 cw(c5449.51,7720.51) 5464,7720.51 cw(c5478.49,7720.51) v3@5468.24,7730.76 ; v3(5464,7735) 5464,7643 5478.05,7628.95 U1.204@5478.05,7585.69 ; v3@5611.6,8789.4 ccw(c5601.36,8799.64) 5615.84,8799.64 ccw(c5630.33,8799.64) v3@5620.09,8789.4 ; U1.211@5615.84,7585.69 5615.84,7693.84 v3(5651,7729) ; v3(5615.84,8785.16) U1.90@5615.84,8922.31 ; v3@5645,7729 cw(c5630.51,7729) 5640.76,7718.76 cw(c5651,7708.51) v3@5651,7723 ; v3@5788.77,7725.77 cw(c5778.52,7715.52) 5793.01,7715.52 cw(c5807.49,7715.52) v3@5797.25,7725.77 ; v3@5788.77,8784.23 ccw(c5778.52,8794.48) 5793.01,8794.48 ccw(c5807.49,8794.48) v3@5797.25,8784.23 ; U1.220@5793.01,7585.69 v3(5793.01,7730.01) ; v3(5793.01,8779.99) U1.81@5793.01,8922.31 ; v3@5933.76,8771.24 ccw(c5923.51,8781.49) 5938,8781.49 ccw(c5952.49,8781.49) v3@5942.24,8771.24 ; v3(5938,8767) 5938,8848 5970.17,8880.17 U1.72@5970.17,8922.31 ; v3@5938.76,7748.76 cw(c5928.51,7738.51) 5943,7738.51 cw(c5957.49,7738.51) v3@5947.24,7748.76 ; v3(5943,7753) 5943,7655 5970.17,7627.83 U1.229@5970.17,7585.69
  TopLayer w40: v3(7022.88,8805.88) 7338.88,8805.88 7375,8842 U9.3@7429,8842 ; 7352.08,8819.08 cw(c7405,8766.16) U9.3@7405,8841 ; 7360,8827 cw(c7395.79,8791.21) U9.3@7404.82,8841.02
  BottomLayer w12: v3@5222.14,8772.86 cw(c5222.14,8758.37) 5232.38,8768.62 cw(c5242.63,8778.86) v3@5228.14,8778.86 ; v3(5222.14,8778.86) 5241,8760 ; v3(5239,7761) 5279,7761 C49.1@5280,7760 ; v3@5243.24,7756.76 cw(c5253.49,7746.51) 5253.49,7761 cw(c5253.49,7775.49) v3@5243.24,7765.24 ; C51.1@5253.04,8754.3 ccw(c5241,8744.45) 5241,8760 ; C51.1@5253.04,8765.7 cw(c5241,8775.55) 5241,8760 ; 5255.86,7761 cw(c5255.86,7735.86) C49.1@5273.64,7753.64 ; C51.1@5260,8760 5241,8760 ; 5260.69,7761 ccw(c5260.69,7779.31) C49.1@5273.64,7766.36 ; v3@5336.6,8766.92 ccw(c5352.47,8781.66) 5352.47,8760 ; v3@5341,8765 cw(c5341,8750.51) 5351.24,8760.76 cw(c5361.49,8771) v3@5347,8771 ; v3(5341,8771) 5352,8760 C53.1@5380,8760 cw(c5380,8807.23) v3@5345.4,8775.08 ; v3(5359.94,7739.94) C52.1@5380,7760 ; v3@5359.94,7745.94 ccw(c5359.94,7760.42) 5370.18,7750.18 ccw(c5380.42,7739.94) v3@5365.94,7739.94 ; v3@5360.37,7740.37 cw(c5380,7720.74) C52.1@5380,7748.5 ; FB6.1@5366,8119.54 v3(5424.54,8119.54) ; C52.1@5366.4,7746.4 ccw(c5355.31,7757.5) C52.1@5371,7757.5 ; C53.1@5373.64,8753.64 ccw(c5358.27,8738.27) 5358.27,8760 ccw(c5358.27,8781.73) C53.1@5373.64,8766.36 ; FB6.1@5375.68,8109.86 cw(c5399.04,8086.5) 5399.04,8119.54 cw(c5399.04,8152.57) FB6.1@5375.68,8129.21 ; v3@5420.29,8115.29 ccw(c5410.05,8105.05) 5410.05,8119.54 ccw(c5410.05,8134.02) v3@5420.29,8123.78 ; v3(5458,8770) 5490,8770 C58.1@5500,8760 ; v3@5460.17,8770 cw(c5460.17,8722.67) C58.1@5493.64,8756.14 ; v3@5461.59,7732.59 cw(c5500,7694.18) C54.1@5500,7748.5 ; v3@5462.24,8765.76 cw(c5472.49,8755.51) 5472.49,8770 cw(c5472.49,8784.49) v3@5462.24,8774.24 ; v3(5464,7735) 5489,7760 C54.1@5500,7760 ; v3@5464,7741 ccw(c5464,7755.49) 5474.24,7745.24 ccw(c5484.49,7735) v3@5470,7735 ; 5482.08,7753.08 cw(c5500,7735.15) C54.1@5500,7760.5 ; v3@5615.84,8779.16 cw(c5615.84,8764.67) 5626.09,8774.91 cw(c5636.33,8785.16) v3@5621.84,8785.16 ; v3(5615.84,8785.16) 5641,8760 ; 5626.59,8774.41 ccw(c5643.78,8791.6) C61.1@5655.62,8770.36 ; 5637.83,8763.17 ccw(c5651.82,8777.17) C61.1@5661.46,8759.88 ; v3@5645.76,7731.93 cw(c5659.53,7724.23) 5659.53,7740 ; v3(5651,7729) 5662,7740 ; v3@5651,7735 ccw(c5651,7749.49) 5661.24,7739.24 ccw(c5671.49,7729) v3@5657,7729 ; v3@5653,7731 cw(c5664.86,7719.14) C60.1@5674.71,7732.72 ; C61.1@5653.04,8754.3 ccw(c5641,8744.45) 5641,8760 ; C61.1@5653.04,8765.7 cw(c5641,8775.55) 5641,8760 ; v3@5655.56,7733.56 cw(c5674.13,7714.99) C60.1@5680.76,7740.4 ; v3@5656.24,7726.07 cw(c5680,7712.77) C60.1@5680,7740 5662,7740 ; C61.1@5660,8760 5641,8760 ; 5662.94,7740.94 cw(c5673.22,7730.66) C60.1@5681.76,7742.43 ; C60.1@5672.8,7734.6 ccw(c5662,7726.5) 5662,7740 ; C60.1@5672.8,7745.4 cw(c5662,7753.5) 5662,7740 ; v3@5787.75,7732.89 cw(c5799.75,7726.32) 5799.75,7740 ; v3(5793.01,7730.01) 5803,7740 ; v3@5793.01,8773.99 cw(c5793.01,8759.51) 5803.25,8769.75 cw(c5813.49,8779.99) v3@5799.01,8779.99 ; v3(5793.01,8779.99) 5813,8760 C64.1@5840,8760 ; v3@5793.11,7736.01 ccw(c5793.36,7749.64) 5803,7740 ; v3@5794.5,7731.5 cw(c5805.29,7720.71) C63.1@5814.54,7732.84 ; v3@5797.47,7734.47 cw(c5814.11,7717.83) C63.1@5820.86,7740.37 ; v3@5798.27,7727.13 cw(c5820,7715.23) C63.1@5820,7740 5803,7740 ; v3@5799.01,7730.11 cw(c5812.64,7730.36) 5803,7740 ; 5804.2,7741.2 cw(c5813.69,7731.72) C63.1@5821.82,7742.39 ; C63.1@5812.56,7734.94 ccw(c5803,7728.45) 5803,7740 ; C63.1@5812.56,7745.06 cw(c5803,7751.55) 5803,7740 ; FB7.1@5813.54,8092.5 cw(c5789.89,8048.33) v3@5840,8048.33 ; FB7.1@5819.2,8103.08 cw(c5800.62,8068.36) 5840,8068.36 ; FB7.1@5820,8106.54 5840,8086.54 v3(5840,8052) ; FB7.1@5822.64,8091.14 cw(c5826.57,8071.14) 5840.98,8085.55 cw(c5858.66,8103.23) FB7.1@5833.68,8104.09 ; FB7.1@5824.87,8113.66 cw(c5811.34,8088.4) 5840,8088.4 ; C64.1@5833.64,8753.64 ccw(c5818.27,8738.27) 5818.27,8760 ccw(c5818.27,8781.73) C64.1@5833.64,8766.36 ; v3@5835.76,8056.24 ccw(c5825.51,8066.49) 5840,8066.49 ccw(c5854.49,8066.49) v3@5844.24,8056.24 ; v3(5938,8767) 5973,8767 C69.1@5980,8760 ; v3@5942.24,8762.76 cw(c5952.49,8752.51) 5952.49,8767 cw(c5952.49,8781.49) v3@5942.24,8771.24 ; v3(5943,7753) 5973,7753 C67.1@5980,7760 ; v3@5947.24,7748.76 cw(c5957.49,7738.51) 5957.49,7753 cw(c5957.49,7767.49) v3@5947.24,7757.24 ; v3@5947.41,7753 ccw(c5947.41,7790.09) C67.1@5973.64,7763.86 ; v3@5947.41,8767 cw(c5947.41,8729.91) C69.1@5973.64,8756.14
  other v3: 7062,8805.88
V2.5: C38.1 C39.2 C40.1 C45.1 C47.1 U1.130 U1.157 U1.172 U18.3 | length 2463.4
  TopLayer w8: v3@4872.61,8120.39 cw(c4886.27,8106.73) 4886.27,8126.05 cw(c4886.27,8145.36) v3@4872.61,8131.7
  TopLayer w12: v3(4866.95,8126.05) U1.157@4937.69,8126.05 ; U1.172@4937.69,7830.77 v3(5000.77,7830.77) ; U1.130@4937.69,8657.54 v3(5000.54,8657.54) ; v3@4996.3,8653.3 ccw(c4986.06,8643.06) 4986.06,8657.54 ccw(c4986.06,8672.03) v3@4996.3,8661.79 ; v3@4996.53,7826.53 ccw(c4986.29,7816.29) 4986.29,7830.77 ccw(c4986.29,7845.26) v3@4996.53,7835.01
  BottomLayer w8: C40.1@4840,8146.5 cw(c4840,8130.81) 4851.1,8141.9 ; C40.1@4840,8160 4840,8153 v3(4866.95,8126.05) ; C40.1@4843,8157.5 ccw(c4861.11,8157.5) C40.1@4848.3,8144.7 ; C40.1@4851,8157.5 ccw(c4888.42,8157.5) v3@4861.96,8131.04 ; v3@4858.95,8126.05 ccw(c4839.64,8126.05) 4853.3,8139.7 ccw(c4866.95,8153.36) v3@4866.95,8134.05 ; v3(5000.54,8657.54) v3@5003,8660
  BottomLayer w12: U18.3@4781,9175 U18.3@4781,9181 ; v3@5003,8660 C47.1@5040,8660 ; v3@5004.79,8653.3 cw(c5020.96,8637.13) 5020.96,8660 ; v3@5005.01,7826.53 cw(c5015.26,7816.29) 5015.26,7830.77 cw(c5015.26,7845.26) v3@5005.01,7835.01 ; C45.1@5024.95,7830.77 ccw(c5024.95,7849.53) C45.1@5039.89,7838.19 ; C45.1@5030.33,7845.44 cw(c5000.77,7867.88) v3(5000.77,7830.77) 5030.77,7830.77 C45.1@5040,7840 ; C47.1@5031.14,8653.64 ccw(c5015.77,8638.27) 5015.77,8660 ccw(c5015.77,8681.73) C47.1@5031.14,8666.36
  BottomLayer w20: v3(4866.95,8126.05) 4931.05,8126.05 4952,8147 ; 4901.54,8657.54 v3(5000.54,8657.54) ; 4952,7832 4999.54,7832 v3(5000.77,7830.77)
  BottomLayer w40: C39.2@4715.47,8919.69 ccw(c4713.02,8941.65) 4735.12,8941.65 ; C39.2@4715.66,8919.78 ccw(c4668.67,8966.76) 4735.12,8966.76 ; 4738.32,9132.32 cw(c4781,9089.64) U18.3@4781,9150 ; U18.3@4781,9175 4735.12,9129.12 4735.12,8941.65 ; 4952,7832 4952,8597 4713.46,8835.54 C39.2@4713.46,8920 4735.12,8941.65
